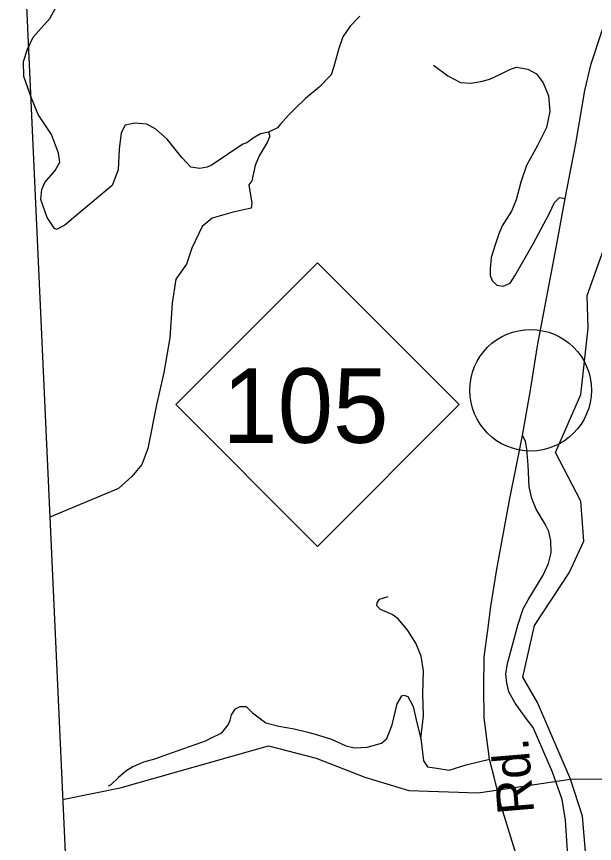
# Model space of a CAD drawing. Extents: x 1190067 to 1192950, y 891516 to 893460.
# Drawn here: x 1190843.1 to 1190890.6, y 893163.2 to 893231.2 of the extents above; entities that cross this region are included whole.
import ezdxf

# ---------------------------------------------------------------- set-up
doc = ezdxf.new("R2010")
doc.units = 0
doc.layers.add('Default', color=7, linetype='Continuous')
doc.layers.add('Prop DSN Text', color=7, linetype='Continuous')

msp = doc.modelspace()

# ---------------------------------------------------------------- linework, layer by layer
at = {"layer": 'Default'}
for p, q in [((1190856.171, 893199.28), (1190867.825, 893210.935)), ((1190867.825, 893210.935), (1190879.48, 893199.28)), ((1190867.825, 893187.626), (1190856.171, 893199.28)), ((1190879.48, 893199.28), (1190867.825, 893187.626))]:
    msp.add_line(p, q, dxfattribs=at)
for points in [[(1190888.631, 893168.483), (1190885.92, 893174.798), (1190884.708, 893176.878), (1190885.66, 893181.124), (1190888.518, 893185.457), (1190889.731, 893188.057), (1190889.471, 893191.35), (1190887.392, 893195.337), (1190889.471, 893200.103), (1190890.077, 893205.563), (1190889.99, 893208.249), (1190891.896, 893213.535), (1190892.588, 893220.079), (1190892.329, 893223.285), (1190893.195, 893228.398), (1190896.745, 893233.078), (1190897.611, 893237.238), (1190897.611, 893240.903), (1190898.391, 893246.103), (1190898.824, 893260.056), (1190899.837, 893262.969), (1190899.376, 893264.324), (1190898.144, 893265.261)], [(1190884.683, 893196.746), (1190885.345, 893200.465), (1190885.907, 893204.127), (1190887.463, 893212.343), (1190888.183, 893216.235), (1190889.062, 893220.762), (1190889.811, 893225.115), (1190890.33, 893227.306), (1190891.237, 893230.045), (1190893.283, 893235.033), (1190894.666, 893238.867), (1190895.299, 893241.26), (1190895.789, 893243.999), (1190895.991, 893247.228), (1190896.236, 893252.561), (1190896.408, 893257.289), (1190896.697, 893260.172), (1190897.158, 893262.508)], [(1190861.687, 893220.695), (1190859.152, 893219.004), (1190858.738, 893218.797), (1190858.152, 893218.693), (1190857.393, 893218.797), (1190856.669, 893219.591), (1190855.461, 893221.109), (1190854.53, 893221.938), (1190853.771, 893222.352), (1190852.805, 893222.421), (1190852.012, 893222.248), (1190851.667, 893221.627), (1190851.495, 893220.281), (1190851.426, 893218.59), (1190850.943, 893217.312), (1190848.114, 893214.931), (1190847.045, 893214.033), (1190846.355, 893213.688), (1190846.183, 893213.757), (1190845.596, 893214.655), (1190845.079, 893216.139), (1190845.148, 893216.967), (1190845.389, 893217.554), (1190846.252, 893218.521), (1190846.631, 893219.211), (1190846.519, 893219.97), (1190845.95, 893221.489), (1190844.846, 893223.146), (1190844.294, 893224.475), (1190843.656, 893226.252), (1190843.648, 893227.495), (1190843.958, 893228.513), (1190844.441, 893229.497), (1190845.096, 893230.222), (1190845.803, 893231.033), (1190846.26, 893231.879)], [(1190871.294, 893231.223), (1190870.5, 893230.394), (1190869.914, 893229.532), (1190869.569, 893228.565), (1190869.155, 893227.081), (1190868.931, 893226.39), (1190867.965, 893225.389), (1190866.827, 893224.458), (1190865.999, 893223.664), (1190865.447, 893223.077), (1190864.757, 893222.317), (1190864.516, 893222.041), (1190863.791, 893221.696), (1190863.136, 893221.558), (1190862.515, 893221.178), (1190861.998, 893220.799), (1190861.687, 893220.695)], [(1190877.353, 893227.182), (1190878.542, 893226.317), (1190879.57, 893225.775), (1190880.435, 893225.721), (1190881.246, 893225.857), (1190882.003, 893226.046), (1190882.977, 893226.506), (1190883.68, 893226.858), (1190884.193, 893227.02), (1190885.113, 893226.858), (1190885.816, 893226.479), (1190886.384, 893225.748), (1190886.816, 893224.666), (1190886.924, 893223.394), (1190886.654, 893222.068), (1190885.924, 893220.58), (1190885.005, 893218.93), (1190884.545, 893217.577), (1190884.166, 893216.116), (1190883.761, 893215.196), (1190883.004, 893213.978), (1190882.693, 893213.248), (1190882.422, 893212.409), (1190882.098, 893211.381), (1190882.017, 893210.434), (1190882.017, 893209.893), (1190882.179, 893209.487), (1190882.558, 893209.108), (1190883.098, 893209.027), (1190883.666, 893209.27), (1190884.045, 893209.865), (1190885.559, 893212.49), (1190886.857, 893214.979), (1190887.316, 893215.899), (1190887.722, 893216.305), (1190888.183, 893216.235)], [(1190863.791, 893221.696), (1190863.886, 893221.342), (1190863.669, 893220.846), (1190863.019, 893219.731), (1190862.679, 893218.956), (1190862.431, 893217.686), (1190862.184, 893217.346), (1190862.431, 893215.859), (1190862.369, 893215.425), (1190860.884, 893215.115), (1190859.15, 893214.62), (1190858.345, 893213.938), (1190857.479, 893212.142), (1190857.045, 893210.841), (1190856.179, 893209.602), (1190855.869, 893207.619), (1190855.683, 893204.77), (1190855.188, 893201.92), (1190854.569, 893199.256), (1190853.857, 893195.663), (1190853.362, 893194.362), (1190852.557, 893193.371), (1190851.443, 893192.379), (1190845.798, 893190.042)], [(1190881.815, 893180.735), (1190882.084, 893182.679), (1190882.558, 893185.748), (1190883.632, 893191.552), (1190884.134, 893194.007), (1190884.683, 893196.746)], [(1190888.419, 893161.736), (1190888.213, 893165.13), (1190887.938, 893166.827), (1190887.147, 893169.052), (1190885.566, 893172.744), (1190884.981, 893173.478), (1190884.064, 893174.74), (1190883.56, 893175.68), (1190883.4, 893176.391), (1190883.308, 893177.125), (1190883.446, 893177.996), (1190883.892, 893179.625), (1190884.282, 893181.161), (1190884.74, 893182.492), (1190885.13, 893183.225), (1190886.368, 893185.267), (1190886.826, 893186.23), (1190887.044, 893187.101), (1190886.998, 893188.088), (1190886.837, 893188.844), (1190886.54, 893189.441), (1190885.806, 893190.679), (1190885.439, 893191.574), (1190885.233, 893192.514), (1190885.142, 893194.303), (1190885.027, 893195.633), (1190884.912, 893196.275), (1190884.683, 893196.746)], [(1190876.325, 893171.822), (1190876.528, 893173.689), (1190876.474, 893175.502), (1190876.528, 893177.396), (1190876.352, 893178.614), (1190875.892, 893179.669), (1190875.244, 893180.724), (1190874.459, 893181.671), (1190873.946, 893182.023), (1190872.999, 893182.429), (1190872.702, 893182.727), (1190872.729, 893182.997), (1190872.918, 893183.295), (1190873.621, 893183.511)], [(1190877.58, 893138.354), (1190879.366, 893141.151), (1190880.453, 893142.808), (1190881.99, 893145.025), (1190883.422, 893147.336), (1190884.565, 893149.902), (1190884.935, 893151.451), (1190885.304, 893153.762), (1190885.466, 893155.126), (1190885.316, 893157.668), (1190884.969, 893159.679), (1190884.149, 893162.291), (1190882.948, 893166.22), (1190882.363, 893168.533), (1190881.963, 893170.145), (1190881.516, 893173.524), (1190881.485, 893176.011), (1190881.513, 893178.55), (1190881.815, 893180.735)], [(1190859.049, 893171.865), (1190859.94, 893172.309), (1190860.48, 893172.959), (1190860.643, 893173.338), (1190860.751, 893173.771), (1190861.075, 893174.258), (1190861.454, 893174.474), (1190861.94, 893174.474), (1190862.481, 893173.933), (1190863.563, 893173.121), (1190864.644, 893172.851), (1190865.888, 893172.634), (1190867.024, 893172.364), (1190867.619, 893172.201), (1190868.971, 893171.768), (1190870.16, 893171.227), (1190870.863, 893171.065), (1190871.891, 893171.119), (1190873.08, 893171.444), (1190873.513, 893171.822), (1190873.946, 893172.959), (1190874.378, 893174.691), (1190874.757, 893175.34), (1190874.919, 893175.394), (1190875.244, 893175.286), (1190875.676, 893174.474), (1190876.001, 893173.121), (1190876.325, 893171.822), (1190876.541, 893169.982), (1190876.866, 893169.495), (1190877.623, 893169.387), (1190878.65, 893169.225), (1190880.056, 893169.658), (1190881.963, 893170.145)], [(1190859.049, 893171.865), (1190858.661, 893171.629), (1190855.875, 893170.665), (1190854.427, 893170.135), (1190853.509, 893169.879), (1190852.627, 893169.508), (1190852.047, 893169.144), (1190851.452, 893168.628), (1190850.814, 893168.035), (1190850.604, 893167.903)], [(1190846.861, 893166.82), (1190851.584, 893167.786), (1190863.799, 893171.22), (1190867.701, 893170.222), (1190871.709, 893168.647)], [(1190871.709, 893168.647), (1190875.331, 893167.543), (1190881.019, 893167.371), (1190888.631, 893168.483)], [(1190918.241, 893157.206), (1190906.289, 893163.073), (1190900.568, 893167.266), (1190897.101, 893168.428), (1190888.631, 893168.483)], [(1190911.295, 893132.126), (1190911.486, 893134.191), (1190910.193, 893139.732), (1190907.374, 893143.923), (1190903.245, 893147.798), (1190901.801, 893148.742), (1190900.515, 893149.173), (1190895.876, 893150.356), (1190894.192, 893151.31), (1190892.866, 893152.6), (1190890.784, 893156.031), (1190889.681, 893158.81), (1190889.883, 893162.225), (1190889.608, 893165.436), (1190888.631, 893168.483)]]:
    msp.add_lwpolyline(points, dxfattribs=at)
at = {"layer": 'Prop DSN Text'}
msp.add_lwpolyline([(1191159.03, 893366.781), (1190838.384, 893352.111), (1190851.291, 893069.992), (1191171.937, 893084.661)], dxfattribs=at)
msp.add_lwpolyline([(1191159.03, 893366.781), (1190838.384, 893352.111), (1190851.291, 893069.992), (1191171.937, 893084.661)], dxfattribs=at)
msp.add_lwpolyline([(1191159.03, 893366.781), (1190838.384, 893352.111), (1190851.291, 893069.992), (1191171.937, 893084.661)], dxfattribs=at)
msp.add_circle((1190885.345, 893200.465), 5, dxfattribs=at)
msp.add_circle((1190885.345, 893200.465), 5, dxfattribs=at)

# ---------------------------------------------------------------- texts
at = {"layer": 'Default'}
msp.add_text('105', height=6.125, dxfattribs=at).set_placement((1190859.99, 893196.141))
msp.add_text('Rd.', height=3, rotation=94.79851, dxfattribs=at).set_placement((1190885.648, 893165.734))

doc.saveas('drawing.dxf')
